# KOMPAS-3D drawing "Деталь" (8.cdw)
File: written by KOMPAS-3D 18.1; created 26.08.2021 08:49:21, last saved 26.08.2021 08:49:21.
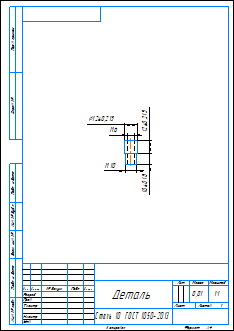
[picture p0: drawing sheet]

Sheet 1: A4, portrait

Document properties: Автор: 111; Полное имя файла: C:\Users\admin\Desktop\ffb\8.cdw; Масса: 0.0119453

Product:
- Part/product: Деталь
    Масса: 0.0119453
  - Component: Отверстие  | qty 2

Title block, sheet 1: Наименование: Деталь; Материал: Сталь 10  ГОСТ 1050-2013; Масса: 0,01; Количество листов документа: 1; Форматы листов документа: A4

Views: Вид 1, Спереди
Referenced files in C:\Users\admin\Desktop\ffb\: t.m3d
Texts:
  Отверстие
Dimensions and other numbers on the sheet: 12±0,215; 6; 10±0,18; 1:1; 1; 0,01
